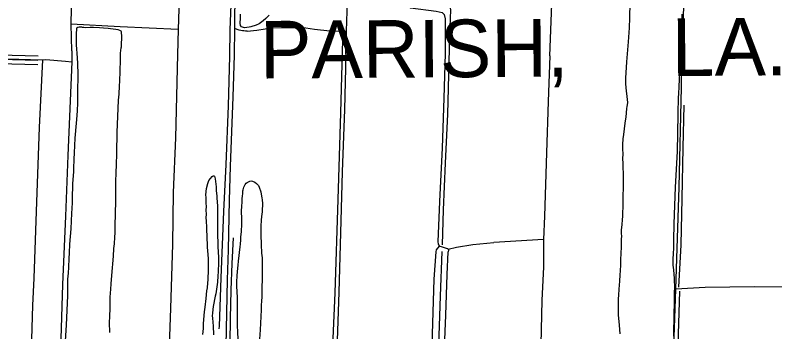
# Model space of a CAD drawing. Extents: x 3508733 to 3546731, y 546897 to 572481.
# Drawn here: x 3529654 to 3532290, y 556457 to 557557 of the extents above; entities that cross this region are included whole.
import ezdxf

# ---------------------------------------------------------------- set-up
doc = ezdxf.new("R2010")
doc.units = 0
for name, color, linetype in [('V-DTCH-CNTR', 7, 'Continuous'), ('V-ROAD-CNTR', 7, 'Continuous'), ('V-SITE-VEGE', 7, 'Continuous'), ('V-TOPO-GNAM-IDEN', 7, 'Continuous'), ('V-TOPO-SHOR', 7, 'Continuous')]:
    doc.layers.add(name, color=color, linetype=linetype)

msp = doc.modelspace()

# ---------------------------------------------------------------- linework, layer by layer
at = {"layer": 'V-DTCH-CNTR'}
for p, q in [((3529851.4, 557432.3), (3529848, 557525.5)), ((3530220.1, 557506.8), (3530217.7, 557419.8)), ((3529829.2, 557396.7), (3529850.6, 557394.9)), ((3531488.1, 556777.7), (3531315.1, 556767.2))]:
    msp.add_line(p, q, dxfattribs=at)
for points in [[(3531509.7, 557415.1), (3531516.2, 557595.4), (3531522.2, 557836.2), (3531528.6, 558064.1), (3531535, 558292), (3531539.8, 558477), (3531548.1, 558711.9), (3531549.9, 558767.1), (3531552.4, 558844.7), (3531557.4, 559049), (3531565.8, 559244), (3531569.2, 559406.1), (3531569.3, 559412), (3531576.9, 559635.2), (3531582.3, 559824.3), (3531589.6, 560016.3), (3531596.2, 560213.1), (3531602.9, 560407.5), (3531608.7, 560629.5), (3531615.5, 560838.5), (3531623.9, 561029.4), (3531629.9, 561207.9), (3531631.6, 561236.7)], [(3530279.3, 559451), (3530269.5, 559164.5), (3530261.9, 558873.5), (3530252, 558576.3), (3530242.8, 558305.5), (3530232.8, 557998.3), (3530227.7, 557760.4), (3530220.1, 557506.8), (3530018.2, 557515.7), (3529848, 557525.5), (3529853.3, 557745.8), (3529861.7, 557968.8), (3529871.3, 558196.8), (3529878.7, 558435.8), (3529882.5, 558693.3), (3529892.9, 558931.5), (3529899.3, 559066.7), (3529908, 559319.9)], [(3531884.1, 554775.9), (3531893.7, 555118.8), (3531909.2, 555499.8), (3531926.1, 555925.7), (3531937.8, 556337.2), (3531946.8, 556604.8), (3531958.6, 556958.8), (3531966.9, 557307.2), (3531969.4, 557459.7), (3531984.5, 557804.6), (3532002.5, 558270.8), (3532020.6, 558748), (3532041.1, 559306.2)], [(3530801.8, 557421.8), (3530804.5, 557500.8), (3530806.8, 557571), (3530812.4, 557769.5), (3530816.3, 557985.7), (3530824.6, 558161.3), (3530829.8, 558329.2), (3530835.8, 558514.2), (3530838.7, 558625.1), (3530839.7, 558664), (3530847, 558860.1), (3530853.4, 559031.6), (3530852.9, 559152.1), (3530851.4, 559183.7)], [(3530453.5, 558853.9), (3530448.8, 558657.3), (3530439.7, 558407.2), (3530432.6, 558118.4), (3530424.2, 557822.8), (3530415.8, 557561.6), (3530415.3, 557510.6), (3530414.5, 557418.2)], [(3531038.1, 558296.4), (3531029.8, 558111.8), (3531024, 557890.8), (3531017.1, 557668.7), (3531014.6, 557598.9), (3531015.7, 557595.4), (3531018.6, 557587.8), (3531025.6, 557582.4), (3531114.6, 557570.4), (3531136.2, 557565.5), (3531143.2, 557559.5), (3531146, 557544.3), (3531146.5, 557423.5)], [(3530459.4, 557500.8), (3530453.8, 557501.2), (3530448.2, 557501.8), (3530442.6, 557502.6), (3530437.1, 557503.7), (3530431.5, 557504.9), (3530415.3, 557510.6)], [(3530459.4, 557500.8), (3530493.4, 557504.5), (3530521.5, 557509.5), (3530549.7, 557513.3), (3530578.9, 557514.2), (3530605.8, 557514.5), (3530634.5, 557513.6), (3530662.6, 557512.7), (3530693.5, 557508.3), (3530746.1, 557502), (3530788.8, 557500.9), (3530804.5, 557500.8)], [(3529851.4, 557432.3), (3529850.6, 557394.9), (3529836.8, 557069.5), (3529828.7, 556858.3), (3529817.9, 556621.5), (3529813, 556432.4), (3529809.1, 556226.7), (3529803.9, 556028.6), (3529798.4, 555884.5), (3529789.3, 555623.5), (3529775.4, 555292.5), (3529766.6, 555085.4), (3529752.5, 554853.6), (3529740.2, 554605.7), (3529736, 554497)], [(3530217.7, 557419.8), (3530210.1, 557130.3), (3530202.4, 556940.6), (3530199.7, 556761.9), (3530193.3, 556537.4), (3530184.9, 556311.7), (3530176.6, 555986.2), (3530164.9, 555699.5), (3530149.8, 555339.4), (3530145.5, 555079.6), (3530135.2, 554827.6), (3530120.7, 554539.6), (3530110.5, 554290.3), (3530105.1, 554043.7), (3530092.7, 553685.7), (3530081.6, 553428.1), (3530080.1, 553420.5), (3530076.5, 553412.9), (3530065.3, 553406.2), (3530036.2, 553407.5), (3529939.2, 553410.7), (3529788.5, 553427.4)], [(3530414.5, 557418.2), (3530409.7, 557273.4), (3530400.2, 557031.1), (3530396.6, 556914), (3530393.3, 556742.2), (3530389.9, 556637), (3530385.6, 556407.7), (3530377, 556176.4), (3530370, 555951.3), (3530359.1, 555667.4), (3530350.2, 555421.5), (3530341.1, 555159.1), (3530333.9, 554891), (3530322.1, 554595.3), (3530314.3, 554367.5), (3530305.1, 554102.3), (3530299.4, 553915.3), (3530294.7, 553740), (3530291, 553654.2), (3530285.8, 553454), (3530280.6, 553361.2), (3530280.1, 553336.3)], [(3530801.8, 557421.8), (3530797, 557228.8), (3530789, 557012.2), (3530784.1, 556841.9), (3530777.4, 556595), (3530768.9, 556359.3), (3530768.2, 556330.1), (3530763.8, 556141), (3530757, 555889.9), (3530750.2, 555661.2), (3530741.5, 555492.6), (3530732.9, 555258.4), (3530725.1, 555023.3), (3530718.4, 554836.8)], [(3531146.5, 557423.5), (3531141.5, 557268.5), (3531135.9, 557095.9), (3531126.7, 556909.5), (3531121.2, 556769.8), (3531121.7, 556762.6), (3531123.3, 556758.7), (3531126.8, 556754.8), (3531133, 556753.1), (3531139.1, 556750.8), (3531149.5, 556748), (3531155, 556746), (3531157.2, 556744.1), (3531157.8, 556740.8), (3531156.9, 556734.3)], [(3529541.8, 557407), (3529749.6, 557401.7), (3529760.7, 557402.2), (3529829.2, 557396.7)], [(3529749.6, 557401.7), (3529737.5, 557167), (3529729.1, 556941.3), (3529719.3, 556643.5), (3529714.7, 556548.6), (3529705.3, 556234.2), (3529697.9, 555955.1), (3529696.6, 555888.6), (3529697.1, 555875.4)], [(3531509.7, 557415.1), (3531504.3, 557256.6), (3531497.7, 557078.7), (3531491.3, 556858.6), (3531488.1, 556777.7)], [(3531157.2, 556744.1), (3531185.8, 556750.7), (3531242.1, 556759.7), (3531315.1, 556767.2)], [(3531488.1, 556777.7), (3531487.3, 556682.5), (3531482.1, 556565.2), (3531478.4, 556414.2), (3531472.1, 556229.7), (3531463, 556025.5), (3531453.9, 555798), (3531445.6, 555581.8), (3531436.6, 555365.6), (3531429.9, 555147.2), (3531420.4, 554914.4), (3531416.5, 554824.7)], [(3531080.8, 554811.6), (3531079.9, 554846), (3531082.3, 554939.4), (3531087.5, 555076.3), (3531093.6, 555224.8), (3531100.3, 555357.9), (3531106.5, 555503), (3531111.3, 555660.8), (3531119.5, 555845), (3531127.7, 556017.9), (3531133.7, 556184.6), (3531141.6, 556344.5), (3531149.2, 556514.4), (3531153.8, 556655.4), (3531156.9, 556734.3)], [(3531098.7, 556334.5), (3531107.9, 556640.2), (3531114.6, 556734.6), (3531116, 556741.5), (3531126.8, 556754.8)], [(3532372.9, 556612.3), (3532220.3, 556613.3), (3532048.3, 556610.8), (3531946.8, 556604.8)]]:
    msp.add_lwpolyline(points, dxfattribs=at)
at = {"layer": 'V-ROAD-CNTR'}
for points in [[(3528204.4, 557444.5), (3528769.9, 557425.5), (3529733.2, 557400.2)], [(3528785.1, 557440.1), (3529733.6, 557415.2)], [(3528784, 557410.2), (3529732.8, 557385.2)]]:
    msp.add_lwpolyline(points, dxfattribs=at)
at = {"layer": 'V-SITE-VEGE'}
for points in [[(3531753.8, 556450), (3531752.7, 556464.4), (3531751, 556479.8), (3531748.2, 556516), (3531747.6, 556550.6), (3531747.9, 556571.4), (3531748.7, 556583.8), (3531750.2, 556604.6), (3531752.4, 556633.1), (3531753.9, 556654.8), (3531755.1, 556668.6), (3531756.3, 556689.4), (3531756.4, 556702.8), (3531757.4, 556734.5), (3531758.2, 556746.6), (3531758.4, 556766.5), (3531758.3, 556770.3), (3531758.4, 556780.2), (3531759.1, 556788.2), (3531758.6, 556799.4), (3531758.7, 556810.3), (3531760.2, 556829.5), (3531762.3, 556845.8), (3531763.4, 556858.9), (3531763, 556874.2), (3531763.8, 556887.7), (3531764.3, 556936.9), (3531764.8, 556949.4), (3531765, 556968.6), (3531764.8, 556981.1), (3531765.1, 557006.4), (3531764.4, 557027.5), (3531764.2, 557040.6), (3531763.5, 557059.8), (3531763.7, 557073.3), (3531763.2, 557093.1), (3531763.4, 557107.8), (3531764.3, 557127), (3531766.7, 557142.4), (3531771.3, 557181.7), (3531774.7, 557203.1), (3531775.5, 557216.5), (3531777.3, 557233.8), (3531777.7, 557238.3), (3531780.1, 557253.3), (3531776.3, 557285), (3531775.1, 557292.4), (3531773.5, 557317.7), (3531772.8, 557338.5), (3531776.9, 557395.1), (3531782.5, 557463.8), (3531786, 557512.8), (3531787.3, 557547), (3531788.9, 557599.4)], [(3530536.2, 557557.3), (3530523.9, 557544.9), (3530514.9, 557537.4), (3530500.7, 557526.6), (3530490.1, 557522), (3530472.1, 557516.1), (3530465.7, 557514.9), (3530450, 557512.8), (3530439.4, 557516.5), (3530436.3, 557521.3), (3530435.4, 557529.3), (3530436.3, 557546.6), (3530436.7, 557559.7)], [(3531967.3, 557560), (3531966.7, 557530.8), (3531965.8, 557510.1), (3531965.2, 557488.9), (3531963.9, 557455.4), (3531962.7, 557433.6), (3531960.1, 557400.7), (3531959.8, 557379.2), (3531959.3, 557359.4), (3531958.3, 557330), (3531957.5, 557313), (3531956.1, 557279.7), (3531955.4, 557274), (3531953.4, 557211.6), (3531951, 557083.3), (3531945.1, 556959.2), (3531940.4, 556831.6), (3531938.8, 556775.2), (3531938.7, 556763.1), (3531938.2, 556744.2), (3531938, 556732.1), (3531936.8, 556705.8), (3531936.6, 556695.3), (3531936.9, 556688.5)], [(3529829.1, 556425.1), (3529832, 556480.4), (3529836.7, 556582.5), (3529837.4, 556639.4), (3529838.9, 556660.5), (3529840.1, 556681.9), (3529841.4, 556711.7), (3529842.6, 556730.9), (3529844.2, 556760.9), (3529848, 556815), (3529849.3, 556842.5), (3529851.2, 556867.4), (3529852.6, 556904.9), (3529852.8, 556929.2), (3529854.2, 556960.9), (3529854.9, 556970.8), (3529857.6, 557013.3), (3529858.1, 557024.2), (3529858.8, 557056.8), (3529860.6, 557078.6), (3529862.8, 557130.1), (3529866.6, 557181.5), (3529868.8, 557208.7), (3529870, 557226), (3529871.2, 557251.2), (3529871.8, 557268.5), (3529872.2, 557307.6), (3529872.8, 557330.9), (3529873, 557348.2), (3529871.9, 557391.1), (3529870.8, 557406.2), (3529869.1, 557426), (3529868.2, 557437.9), (3529867.5, 557454.5), (3529866.7, 557466.4), (3529866.5, 557485.2), (3529867, 557496.1), (3529867.7, 557504.8), (3529868.1, 557513.1), (3529871.4, 557514.6), (3529876.8, 557516.2), (3529884.2, 557516.1), (3529886.7, 557515.4), (3529892.8, 557515), (3529899.5, 557514.3), (3529914.3, 557515.1), (3529926.1, 557515)], [(3529926.1, 557515), (3529946.9, 557514.4), (3529961, 557513.3), (3529977.3, 557511.2), (3529985.3, 557510.8), (3530003.1, 557507.7), (3530010.8, 557507), (3530016.5, 557505), (3530020.7, 557502), (3530022.2, 557499.5), (3530022.2, 557495.9), (3530023, 557485.1), (3530022.6, 557448.9), (3530022.3, 557445.1), (3530021.3, 557441.9), (3530020.2, 557434.8), (3530019.1, 557423.3), (3530018.2, 557401.3), (3530017.8, 557362.2), (3530015.8, 557328), (3530014.7, 557311.7), (3530013.7, 557282.9), (3530011.8, 557261.8), (3530009, 557205.2), (3530007.1, 557150.8), (3530006.2, 557077.8), (3530004.8, 557035.3), (3530003.5, 557011), (3530002.5, 556977.1), (3530001.9, 556925.2), (3530002.3, 556904.4), (3530001.7, 556874), (3530001.6, 556865.7), (3530000.8, 556853.6), (3530000.3, 556839.2), (3530000.1, 556823.8), (3529999.5, 556800.8), (3529998.4, 556785.4), (3529997.5, 556762.1), (3529996, 556746.4), (3529993.8, 556719.6), (3529988.6, 556652.7)], [(3530305.9, 556448.1), (3530307.5, 556468.9), (3530308, 556486.2), (3530311.6, 556525.8), (3530313.7, 556542.8), (3530317.3, 556572.8), (3530319.8, 556598.7), (3530321.2, 556609.9), (3530322.7, 556626.8), (3530323.5, 556638), (3530323.9, 556649.2), (3530325, 556661.4), (3530325.4, 556692.7), (3530324.6, 556710.3), (3530322.7, 556738.8), (3530321.9, 556749.4), (3530321.1, 556765.7), (3530320.9, 556776.6), (3530320.1, 556794.5), (3530319.3, 556805.1), (3530319.4, 556818.2), (3530319.2, 556825.3), (3530318.4, 556836.8), (3530318.4, 556841), (3530317.6, 556854.4), (3530317.7, 556864.7), (3530317.6, 556881), (3530317.7, 556891.2), (3530317.6, 556904.7), (3530317, 556912.7), (3530316.8, 556924.2), (3530316.3, 556931.2), (3530317.4, 556944.4), (3530318.4, 556954.3), (3530322.8, 556972.1), (3530326.4, 556982), (3530331.7, 556990), (3530337.8, 556996.6), (3530341, 556999.1), (3530343.9, 556998.5), (3530345.5, 556997.2), (3530348.6, 556988.5), (3530349.4, 556978.6), (3530351.5, 556960.9), (3530352.3, 556948.1), (3530354, 556928.6), (3530354.2, 556921.9), (3530355.8, 556893.7), (3530356.6, 556847.3), (3530356.1, 556803.7), (3530356.3, 556790.3), (3530357, 556768.8), (3530357.8, 556754.4), (3530358.5, 556732.3), (3530359.3, 556717.6), (3530359.4, 556697.8), (3530359, 556665.1), (3530357.9, 556651.7), (3530356.3, 556629), (3530350.4, 556588.4), (3530348.4, 556581.1), (3530341.3, 556544.7), (3530338.5, 556523), (3530337.5, 556510.7), (3530338.6, 556505), (3530340, 556489.7), (3530340.8, 556477.5), (3530342.7, 556446.1)], [(3530434.9, 556752), (3530435.6, 556761.9), (3530437.4, 556775.9), (3530437.8, 556785.2), (3530439.3, 556805.7), (3530440.6, 556830.9), (3530440.7, 556845), (3530440.5, 556854.9), (3530439.7, 556870.3), (3530439.8, 556878.9), (3530440.3, 556890.1), (3530442.1, 556910.6), (3530442.2, 556918.3), (3530442.7, 556929.2), (3530443.7, 556936.5), (3530444.8, 556946.4), (3530445.4, 556949.9), (3530447.8, 556959.8), (3530452.1, 556968.4), (3530455.3, 556972.9), (3530459.8, 556976), (3530468.5, 556980.4), (3530473.6, 556981), (3530478.1, 556980.3), (3530486.1, 556976.7), (3530492.1, 556972.4), (3530498.1, 556965.3), (3530500.9, 556959.9), (3530506.5, 556943.5), (3530508.3, 556935.1), (3530510.4, 556922.6), (3530511.3, 556914.9), (3530512.4, 556902.4), (3530512.3, 556894.8), (3530511.9, 556883.6), (3530510.8, 556874), (3530508.7, 556857.4), (3530507.6, 556844.3), (3530506.7, 556823.8), (3530506.6, 556810.3), (3530507, 556792.7), (3530506.9, 556781.9), (3530507.4, 556771.3), (3530507.6, 556760.4), (3530509.5, 556730.3), (3530510.9, 556713.3), (3530511.3, 556692.8), (3530511.2, 556684.5), (3530510.8, 556671.7), (3530509.7, 556578.6), (3530509.2, 556563.6), (3530508.4, 556549.2), (3530507.9, 556533.2), (3530507, 556509.8), (3530504.9, 556464.1), (3530500.5, 556414.8)], [(3530428, 556429.1), (3530426.7, 556457.6), (3530426.3, 556476.2), (3530425.9, 556502.4), (3530426.1, 556519.4), (3530426.1, 556543.7), (3530426.3, 556559.7), (3530425.8, 556576.4), (3530424, 556615.4), (3530423.9, 556630.1), (3530424.4, 556651.9), (3530425.6, 556666.3), (3530428.1, 556688), (3530429.5, 556702.7), (3530434.9, 556752)], [(3531936.9, 556688.5), (3531938.6, 556672.5), (3531941.5, 556642.4), (3531941.3, 556630.6), (3531941.8, 556618.7), (3531941.5, 556586.1), (3531940.9, 556563.4), (3531940.7, 556549), (3531940.1, 556526.6), (3531939.8, 556494.2), (3531938.9, 556469.3), (3531938.2, 556442.1)], [(3529988.6, 556652.7), (3529985.7, 556624), (3529984.5, 556605.4), (3529982.9, 556577.3), (3529982.5, 556539.2), (3529981.5, 556509.8), (3529980.9, 556489), (3529981.5, 556454.1)]]:
    msp.add_lwpolyline(points, dxfattribs=at)
at = {"layer": 'V-TOPO-SHOR'}
msp.add_line((3530361.6, 556477), (3530361.4, 556467.6), dxfattribs=at)
for points in [[(3530407.9, 557737.8), (3530399.4, 557506.1), (3530398.4, 557414.1)], [(3531023.8, 557593.3), (3531138.3, 557591.7), (3531157.5, 557589.6), (3531162.9, 557585.2), (3531165.2, 557575.8), (3531161.9, 557484.9)], [(3530790.6, 557471.3), (3530783.5, 557218), (3530773.5, 556916), (3530763.7, 556592.2), (3530750.9, 556302), (3530744.1, 556039.2), (3530729.7, 555691.2), (3530720.2, 555368.5), (3530705.9, 555005.2), (3530701.6, 554849.2)], [(3531161.9, 557484.9), (3531159.6, 557394.9), (3531154.2, 557212.4), (3531146.5, 557043), (3531139.4, 556880.4), (3531136.1, 556759.6)], [(3530398.4, 557414.1), (3530393.3, 557241.8), (3530384.9, 557038.3), (3530377.6, 556875.3), (3530368.4, 556644.2), (3530361.6, 556477)], [(3531957.7, 556612.1), (3531965, 556758.9), (3531968.3, 556919.7), (3531972.4, 557095.6), (3531975.6, 557243.9)], [(3530410.5, 556783.3), (3530406.4, 556693.7), (3530402.7, 556601.4), (3530399.9, 556503.1), (3530399.5, 556418.7)], [(3531135.4, 556736.1), (3531129, 556581.1), (3531119.4, 556306.5), (3531111.4, 556086.3), (3531098.1, 555804.9), (3531087.2, 555563.1), (3531076.1, 555269.7), (3531064.4, 554926.6), (3531062, 554824.8), (3531061.9, 554822.2)], [(3531862, 553672.2), (3531859.3, 553674.3), (3531860.1, 553686.1), (3531867.3, 553882.1), (3531875.2, 554087.2), (3531882.3, 554276.3), (3531890.1, 554525.7), (3531898.3, 554808.3), (3531905.4, 555113.8), (3531917.8, 555399.2), (3531927.7, 555652.7), (3531940.1, 556002.5), (3531952, 556299.6), (3531961, 556598.2)]]:
    msp.add_lwpolyline(points, dxfattribs=at)

# ---------------------------------------------------------------- texts
at = {"layer": 'V-TOPO-GNAM-IDEN'}
for s, rotation, p in [('PARISH,', 0.3801, (3530504.5, 557336.6)), ('LA.', 0.3657, (3531933.1, 557345.2))]:
    msp.add_text(s, height=200, rotation=rotation, dxfattribs=at).set_placement(p)

doc.saveas('drawing.dxf')
